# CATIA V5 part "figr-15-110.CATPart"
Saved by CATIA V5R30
Part number: Part1
Bounding box of the stored display mesh (mm): x 0.737 to 206.429, y 0 to 112.04, z -1 to 2
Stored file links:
  D:\PROJECTS\CATIA V56R 2020\Resources\Parts File\c15_catia_v5_6r2020_prt\figr-15-110.CATPart
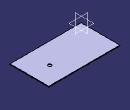
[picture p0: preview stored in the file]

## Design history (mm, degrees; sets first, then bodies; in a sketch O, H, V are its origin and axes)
SheetMetalParameters1: Thickness 2, BendRadius 4, KFactor 0.400515 {= log(min(100,max(20*SheetMetalParameters1.BendRadius,SheetMetalParameters1.Thickness)/SheetMetalParameters1.Thickness))/log(100)/2}, ReliefRadialLength 1, ReliefAxialLength 2, MinimumBendRadius 0
Body1 (main body)
  Sketch1 on xy-plane, origin (0, 0, 0), H (1, 0, 0), V (0, 1, 0)
    line L1 (0.7372, 112.0403) -> (206.4285, 112.0403)
    line L2 (206.4285, 112.0403) -> (206.4285, 0)
    line L3 (206.4285, 0) -> (0.7372, 0)
    line L4 (0.7372, 0) -> (0.7372, 112.0403)
    horizontal: L1 H, L3 H
    vertical: L2 V, L4 V
  Wall1: Thickness 2, Profile Sketch1, OffsetValue 0
  Sketch2 on face of Wall1, origin (152.409, 60.7083, 2), H (1, 0, 0), V (0, 1, 0)
    point P1 (0, 0)
  d_Stamp1: KFacteur 0.400515 {= SheetMetalParameters1.KFactor}, NewRoot_AttribNormalisation "No Standard", Stamp_FilletActivity false, Stamp_FilletRadius 2, Stamp_IntersectFilletRadius 2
